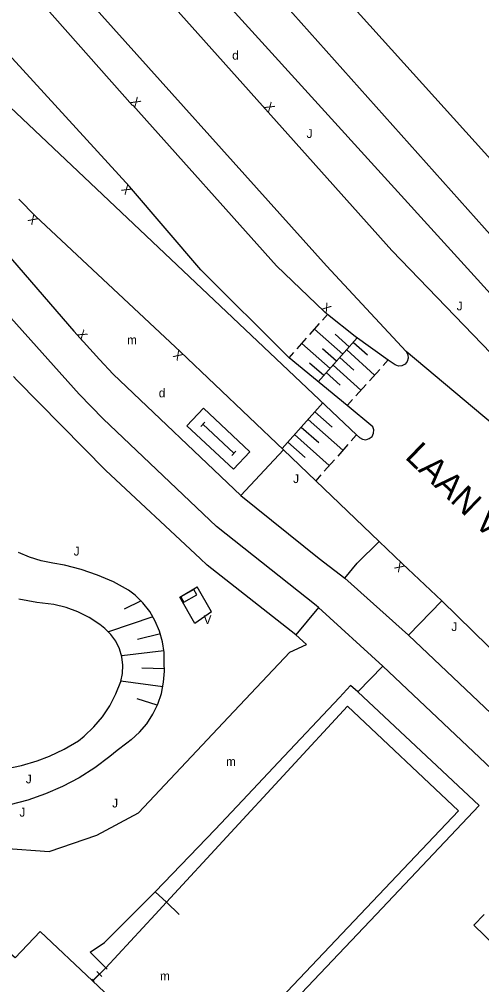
# Model space of a CAD drawing. Extents: x 134999 to 136502, y 457398 to 459002.
# Drawn here: x 135226.5 to 135252.6, y 457796 to 457850.6 of the extents above; entities that cross this region are included whole.
import ezdxf

# ---------------------------------------------------------------- set-up
doc = ezdxf.new("R2010")
doc.units = 0
for name, color, linetype in [('RI_DGTB_18', 7, 'Continuous'), ('RI_DGTB_2', 7, 'Continuous'), ('RI_DGTB_29', 7, 'Continuous'), ('RI_DGTB_30', 7, 'Continuous'), ('RI_DGTB_31', 7, 'Continuous'), ('RI_DGTB_37', 7, 'Continuous'), ('RI_DGTB_43', 7, 'Continuous'), ('RI_DGTB_48', 7, 'Continuous'), ('RI_DGTB_53', 7, 'Continuous'), ('RI_DGTB_58', 7, 'Continuous')]:
    doc.layers.add(name, color=color, linetype=linetype)

msp = doc.modelspace()

# ---------------------------------------------------------------- linework, layer by layer
at = {"layer": 'RI_DGTB_18'}
for p, q in [((135233.386, 457817.734), (135232.425, 457817.267)), ((135233.386, 457817.734), (135232.425, 457817.267)), ((135234.063, 457816.825), (135231.542, 457815.977)), ((135234.063, 457816.825), (135231.542, 457815.977)), ((135234.48, 457815.874), (135233.195, 457815.554)), ((135234.48, 457815.874), (135233.195, 457815.554)), ((135234.679, 457814.901), (135232.294, 457814.618)), ((135234.679, 457814.901), (135232.294, 457814.618)), ((135234.709, 457813.879), (135233.426, 457813.917)), ((135234.709, 457813.879), (135233.426, 457813.917)), ((135234.621, 457812.878), (135232.254, 457813.185)), ((135234.621, 457812.878), (135232.254, 457813.185)), ((135234.306, 457811.832), (135233.176, 457812.185)), ((135234.306, 457811.832), (135233.176, 457812.185))]:
    msp.add_line(p, q, dxfattribs=at)
for points in [[(135232.826, 457809.864), (135233.295, 457810.297), (135233.707, 457810.785), (135234.054, 457811.321), (135234.332, 457811.896), (135234.535, 457812.501), (135234.662, 457813.127), (135234.709, 457813.764), (135234.696, 457814.188), (135234.687, 457814.808), (135234.599, 457815.421), (135234.432, 457816.018), (135234.19, 457816.588), (135233.876, 457817.123), (135233.497, 457817.613), (135233.057, 457818.049), (135232.688, 457818.341), (135231.826, 457818.802), (135230.929, 457819.192), (135230.003, 457819.507), (135229.054, 457819.745), (135228.409, 457819.861), (135227.739, 457819.989), (135227.088, 457820.195), (135226.466, 457820.476)], [(135232.826, 457809.864), (135233.295, 457810.297), (135233.707, 457810.785), (135234.054, 457811.321), (135234.332, 457811.896), (135234.535, 457812.501), (135234.662, 457813.127), (135234.709, 457813.764), (135234.696, 457814.188), (135234.687, 457814.808), (135234.599, 457815.421), (135234.432, 457816.018), (135234.19, 457816.588), (135233.876, 457817.123), (135233.497, 457817.613), (135233.057, 457818.049), (135232.688, 457818.341), (135231.826, 457818.802), (135230.929, 457819.192), (135230.003, 457819.507), (135229.054, 457819.745), (135228.409, 457819.861), (135227.739, 457819.989), (135227.088, 457820.195), (135226.466, 457820.476)], [(135236.365, 457818.379), (135235.633, 457817.961), (135235.811, 457817.65), (135236.542, 457818.068), (135236.365, 457818.379)], [(135236.365, 457818.379), (135235.633, 457817.961), (135235.811, 457817.65), (135236.542, 457818.068), (135236.365, 457818.379)], [(135232.826, 457809.864), (135232.587, 457809.675), (135232.036, 457809.264), (135231.626, 457808.921), (135230.778, 457808.292), (135229.885, 457807.728), (135228.952, 457807.234), (135227.984, 457806.812), (135226.987, 457806.464), (135225.966, 457806.193), (135224.928, 457805.999), (135223.878, 457805.885), (135223.36, 457805.868)], [(135232.826, 457809.864), (135232.587, 457809.675), (135232.036, 457809.264), (135231.626, 457808.921), (135230.778, 457808.292), (135229.885, 457807.728), (135228.952, 457807.234), (135227.984, 457806.812), (135226.987, 457806.464), (135225.966, 457806.193), (135224.928, 457805.999), (135223.878, 457805.885), (135223.36, 457805.868)]]:
    msp.add_lwpolyline(points, dxfattribs=at)
at = {"layer": 'RI_DGTB_2'}
for points in [[(135230.648, 457796.241), (135227.689, 457799.035), (135226.273, 457797.536), (135226.034, 457797.754), (135225.913, 457797.626)], [(135234.624, 457792.299), (135234.718, 457792.398), (135230.648, 457796.241)]]:
    msp.add_lwpolyline(points, dxfattribs=at)
at = {"layer": 'RI_DGTB_29'}
for points in [[(135238.604, 457825.177), (135239.538, 457826.167), (135236.912, 457828.626), (135235.98, 457827.634), (135238.604, 457825.177)], [(135238.604, 457825.177), (135239.538, 457826.167), (135236.912, 457828.626), (135235.98, 457827.634), (135238.604, 457825.177)], [(135236.768, 457827.598), (135237.001, 457827.847)], [(135236.768, 457827.598), (135237.001, 457827.847)], [(135236.885, 457827.72), (135238.633, 457826.082)], [(135236.885, 457827.72), (135238.633, 457826.082)], [(135238.516, 457825.956), (135238.748, 457826.205)], [(135238.516, 457825.956), (135238.748, 457826.205)]]:
    msp.add_lwpolyline(points, dxfattribs=at)
at = {"layer": 'RI_DGTB_31'}
for p, q in [((135243.648, 457833.616), (135243.919, 457833.921)), ((135243.648, 457833.616), (135243.919, 457833.921)), ((135242.927, 457832.801), (135243.468, 457833.412)), ((135242.927, 457832.801), (135243.468, 457833.412)), ((135244.793, 457831.693), (135243.197, 457833.106)), ((135244.793, 457831.693), (135243.197, 457833.106)), ((135245.154, 457832.1), (135244.356, 457832.807)), ((135245.154, 457832.1), (135244.356, 457832.807)), ((135242.205, 457831.986), (135242.746, 457832.597)), ((135242.205, 457831.986), (135242.746, 457832.597)), ((135244.071, 457830.878), (135242.476, 457832.292)), ((135244.071, 457830.878), (135242.476, 457832.292)), ((135243.405, 457830.126), (135245.599, 457832.603)), ((135243.405, 457830.126), (135245.599, 457832.603)), ((135245.396, 457832.352), (135246.185, 457831.641)), ((135245.396, 457832.352), (135246.185, 457831.641)), ((135241.754, 457831.477), (135242.025, 457831.782)), ((135241.754, 457831.477), (135242.025, 457831.782)), ((135244.432, 457831.286), (135243.634, 457831.992)), ((135244.432, 457831.286), (135243.634, 457831.992)), ((135245.011, 457831.924), (135246.589, 457830.502)), ((135245.011, 457831.924), (135246.589, 457830.502)), ((135243.71, 457830.471), (135242.913, 457831.178)), ((135243.71, 457830.471), (135242.913, 457831.178)), ((135244.24, 457831.07), (135245.818, 457829.648)), ((135244.24, 457831.07), (135245.818, 457829.648)), ((135244.626, 457831.497), (135245.415, 457830.786)), ((135244.626, 457831.497), (135245.415, 457830.786)), ((135247.359, 457831.357), (135247.07, 457831.036)), ((135247.359, 457831.357), (135247.07, 457831.036)), ((135243.855, 457830.642), (135244.644, 457829.931)), ((135243.855, 457830.642), (135244.644, 457829.931)), ((135246.878, 457830.823), (135246.3, 457830.182)), ((135246.878, 457830.823), (135246.3, 457830.182)), ((135246.107, 457829.968), (135245.529, 457829.327)), ((135246.107, 457829.968), (135245.529, 457829.327)), ((135243.653, 457828.927), (135241.366, 457826.349)), ((135243.653, 457828.927), (135241.366, 457826.349)), ((135245.337, 457829.114), (135245.048, 457828.793)), ((135245.337, 457829.114), (135245.048, 457828.793)), ((135243.205, 457828.421), (135244.189, 457827.548)), ((135243.205, 457828.421), (135244.189, 457827.548)), ((135242.824, 457827.992), (135244.791, 457826.246)), ((135242.824, 457827.992), (135244.791, 457826.246)), ((135242.443, 457827.563), (135243.427, 457826.69)), ((135242.443, 457827.563), (135243.427, 457826.69)), ((135241.681, 457826.704), (135242.665, 457825.831)), ((135241.681, 457826.704), (135242.665, 457825.831)), ((135242.062, 457827.133), (135244.029, 457825.388)), ((135242.062, 457827.133), (135244.029, 457825.388)), ((135245.553, 457827.105), (135245.267, 457826.783)), ((135245.553, 457827.105), (135245.267, 457826.783)), ((135245.077, 457826.568), (135244.505, 457825.924)), ((135245.077, 457826.568), (135244.505, 457825.924)), ((135244.315, 457825.71), (135243.743, 457825.066)), ((135244.315, 457825.71), (135243.743, 457825.066)), ((135243.553, 457824.851), (135243.267, 457824.529)), ((135243.553, 457824.851), (135243.267, 457824.529))]:
    msp.add_line(p, q, dxfattribs=at)
at = {"layer": 'RI_DGTB_48'}
for p, q in [((135231.4, 457796.978), (135230.648, 457796.241)), ((135231.4, 457796.978), (135230.674, 457796.266)), ((135230.895, 457796.767), (135231.179, 457796.477)), ((135231.329, 457797.051), (135231.471, 457796.906)), ((135230.602, 457796.339), (135230.745, 457796.194))]:
    msp.add_line(p, q, dxfattribs=at)
for points in [[(135245.777, 457800), (135251.328, 457805.855), (135245.048, 457811.777), (135234.818, 457800.684)], [(135245.777, 457800), (135251.328, 457805.855), (135245.048, 457811.777), (135234.818, 457800.684)], [(135234.818, 457800.684), (135234.187, 457800)], [(135234.818, 457800.684), (135234.187, 457800)], [(135224.781, 457777.855), (135245.777, 457800)], [(135234.187, 457800), (135231.4, 457796.978)]]:
    msp.add_lwpolyline(points, dxfattribs=at)
at = {"layer": 'RI_DGTB_53'}
for p, q in [((135241.436, 457826.282), (135239.029, 457823.682)), ((135241.436, 457826.282), (135239.029, 457823.682)), ((135248.495, 457815.799), (135244.907, 457819.008)), ((135248.495, 457815.799), (135244.907, 457819.008)), ((135250.386, 457817.74), (135248.495, 457815.799)), ((135250.386, 457817.74), (135248.495, 457815.799)), ((135256.577, 457811.657), (135250.386, 457817.74)), ((135256.577, 457811.657), (135250.386, 457817.74)), ((135243.419, 457817.363), (135242.141, 457815.804)), ((135243.419, 457817.363), (135242.141, 457815.804)), ((135247.057, 457814.035), (135243.419, 457817.363)), ((135247.057, 457814.035), (135243.419, 457817.363)), ((135248.495, 457815.799), (135255.373, 457809.277)), ((135248.495, 457815.799), (135255.373, 457809.277)), ((135247.057, 457814.035), (135245.634, 457812.582)), ((135247.057, 457814.035), (135245.634, 457812.582)), ((135254.543, 457806.938), (135247.057, 457814.035)), ((135254.543, 457806.938), (135247.057, 457814.035)), ((135245.634, 457812.582), (135252.496, 457806.153)), ((135245.634, 457812.582), (135252.496, 457806.153))]:
    msp.add_line(p, q, dxfattribs=at)
for points in [[(135262.084, 457829.306), (135259.895, 457831.332), (135255.632, 457835.649), (135218.403, 457877.368), (135217.92, 457878.412), (135217.51, 457879.486), (135217.176, 457880.587), (135216.92, 457881.708), (135216.742, 457882.844), (135216.643, 457883.99), (135216.624, 457885.14), (135216.685, 457886.288), (135216.826, 457887.43), (135217.046, 457888.559), (135217.344, 457889.67), (135217.718, 457890.757), (135218.167, 457891.816), (135218.689, 457892.841), (135219.28, 457893.828), (135219.484, 457894.135), (135220.596, 457896.004)], [(135214.308, 457869.684), (135214.517, 457869.524), (135229.194, 457853.064), (135243.866, 457836.688), (135248.375, 457831.827)], [(135254.018, 457841.725), (135228.805, 457869.703)], [(135243.928, 457833.931), (135243.731, 457834.089), (135241.042, 457836.69), (135232.933, 457845.76), (135232.913, 457845.748), (135213.574, 457867.578), (135213.061, 457868.14)], [(135241.761, 457831.485), (135241.728, 457831.512), (135236.775, 457836.464), (135232.736, 457841.175), (135213.03, 457862.732)], [(135231.424, 457858.338), (135231.738, 457858.525), (135231.868, 457858.521), (135231.972, 457858.444), (135254.459, 457833.654), (135260.855, 457827.225)], [(135230.086, 457857.141), (135247.557, 457837.552), (135253.693, 457831.203), (135259.46, 457825.55)], [(135243.419, 457817.363), (135243.294, 457817.477), (135237.651, 457821.934), (135231.247, 457828.034), (135229.888, 457829.418), (135222.146, 457838.055), (135220.907, 457839.356), (135219.612, 457840.6), (135218.263, 457841.785), (135216.862, 457842.909), (135215.413, 457843.969), (135213.917, 457844.964), (135212.379, 457845.891), (135210.802, 457846.749), (135209.187, 457847.536), (135208.738, 457847.739), (135202.359, 457850.382), (135202.344, 457850.386)], [(135224.564, 457846.994), (135245.564, 457827.118)], [(135226.49, 457840.445), (135227.431, 457839.492), (135235.627, 457831.811), (135241.436, 457826.282)], [(135224.67, 457838.656), (135229.595, 457832.986), (135231.048, 457831.377), (135231.814, 457830.554), (135239.029, 457823.682)], [(135247.353, 457831.351), (135245.489, 457832.681), (135243.928, 457833.931)], [(135247.353, 457831.351), (135245.489, 457832.681), (135243.928, 457833.931)], [(135248.375, 457831.827), (135248.471, 457831.653), (135248.492, 457831.455), (135248.434, 457831.265), (135248.306, 457831.113), (135248.129, 457831.022), (135247.931, 457831.008), (135247.743, 457831.073), (135247.353, 457831.351)], [(135248.375, 457831.827), (135248.471, 457831.653), (135248.492, 457831.455), (135248.434, 457831.265), (135248.306, 457831.113), (135248.129, 457831.022), (135247.931, 457831.008), (135247.743, 457831.073), (135247.353, 457831.351)], [(135273.961, 457811.511), (135263.706, 457818.967), (135248.375, 457831.827)], [(135273.961, 457811.511), (135263.706, 457818.967), (135248.375, 457831.827)], [(135245.035, 457828.778), (135241.761, 457831.485)], [(135245.035, 457828.778), (135241.761, 457831.485)], [(135236.73, 457820.135), (135231.407, 457825.105), (135226.366, 457830.218), (135226.186, 457830.423)], [(135236.73, 457820.135), (135231.407, 457825.105), (135226.366, 457830.218), (135226.186, 457830.423)], [(135245.564, 457827.118), (135245.727, 457826.964), (135245.901, 457826.868), (135246.099, 457826.848), (135246.289, 457826.906), (135246.441, 457827.034), (135246.531, 457827.211), (135246.545, 457827.41), (135246.495, 457827.571), (135245.035, 457828.778)], [(135245.564, 457827.118), (135245.727, 457826.964), (135245.901, 457826.868), (135246.099, 457826.848), (135246.289, 457826.906), (135246.441, 457827.034), (135246.531, 457827.211), (135246.545, 457827.41), (135246.495, 457827.571), (135245.035, 457828.778)], [(135241.436, 457826.282), (135243.265, 457824.527)], [(135241.436, 457826.282), (135243.265, 457824.527)], [(135243.265, 457824.527), (135246.849, 457821.088)], [(135243.265, 457824.527), (135246.849, 457821.088)], [(135239.029, 457823.682), (135243.463, 457820.121), (135244.907, 457819.008)], [(135239.029, 457823.682), (135243.463, 457820.121), (135244.907, 457819.008)], [(135244.907, 457819.008), (135245.598, 457819.859), (135246.849, 457821.088)], [(135244.907, 457819.008), (135245.598, 457819.859), (135246.849, 457821.088)], [(135246.849, 457821.088), (135248.145, 457819.844), (135250.386, 457817.74)], [(135246.849, 457821.088), (135248.145, 457819.844), (135250.386, 457817.74)], [(135237.657, 457819.345), (135237.133, 457819.759), (135236.73, 457820.135)], [(135237.657, 457819.345), (135237.133, 457819.759), (135236.73, 457820.135)], [(135242.141, 457815.804), (135237.657, 457819.345)], [(135242.141, 457815.804), (135237.657, 457819.345)], [(135237.379, 457817.104), (135236.426, 457816.453), (135235.578, 457817.933), (135236.565, 457818.525)], [(135237.379, 457817.104), (135236.426, 457816.453), (135235.578, 457817.933), (135236.565, 457818.525)], [(135237.379, 457817.104), (135236.565, 457818.525)], [(135237.379, 457817.104), (135236.565, 457818.525)], [(135242.73, 457815.26), (135242.141, 457815.804)], [(135242.73, 457815.26), (135242.141, 457815.804)], [(135225.621, 457803.752), (135228.19, 457803.546), (135230.892, 457804.477), (135233.248, 457805.742), (135238.325, 457811.161), (135241.792, 457814.833), (135242.73, 457815.26)], [(135225.621, 457803.752), (135228.19, 457803.546), (135230.892, 457804.477), (135233.248, 457805.742), (135238.325, 457811.161), (135241.792, 457814.833), (135242.73, 457815.26)], [(135234.19, 457801.28), (135237.582, 457804.805), (135239.124, 457806.432), (135241.15, 457808.599), (135244.613, 457812.273), (135245.235, 457812.95)], [(135234.19, 457801.28), (135237.582, 457804.805), (135239.124, 457806.432), (135241.15, 457808.599), (135244.613, 457812.273), (135245.235, 457812.95)], [(135245.634, 457812.582), (135245.235, 457812.95)], [(135245.634, 457812.582), (135245.235, 457812.95)], [(135246.668, 457800), (135252.496, 457806.153)], [(135246.668, 457800), (135252.496, 457806.153)], [(135232.911, 457800), (135234.19, 457801.28)], [(135232.911, 457800), (135234.19, 457801.28)], [(135234.818, 457800.684), (135234.19, 457801.28)], [(135234.818, 457800.684), (135234.19, 457801.28)], [(135235.539, 457800), (135234.818, 457800.684)], [(135235.539, 457800), (135234.818, 457800.684)], [(135224.115, 457777.274), (135224.71, 457776.706), (135239.621, 457792.561), (135246.668, 457800)], [(135231.4, 457796.978), (135230.513, 457797.861), (135231.329, 457798.417), (135232.911, 457800)], [(135252.783, 457800), (135252.196, 457799.392), (135257.65, 457794.108), (135268.337, 457783.81), (135273.74, 457778.626)]]:
    msp.add_lwpolyline(points, dxfattribs=at)
at = {"layer": 'RI_DGTB_58'}
msp.add_lwpolyline([(135225.723, 457808.223), (135226.633, 457808.413), (135227.523, 457808.68), (135228.211, 457808.945), (135229.048, 457809.344), (135229.848, 457809.814), (135230.182, 457810.085), (135230.722, 457810.605), (135231.204, 457811.179), (135231.621, 457811.802), (135231.971, 457812.465), (135232.247, 457813.162), (135232.344, 457813.615), (135232.365, 457814.091), (135232.306, 457814.563), (135232.169, 457815.019), (135231.958, 457815.445), (135231.678, 457815.83), (135231.338, 457816.163), (135231.052, 457816.389), (135230.456, 457816.782), (135229.82, 457817.106), (135229.151, 457817.356), (135228.459, 457817.531), (135227.49, 457817.636), (135226.483, 457817.823)], dxfattribs=at)
msp.add_lwpolyline([(135225.723, 457808.223), (135226.633, 457808.413), (135227.523, 457808.68), (135228.211, 457808.945), (135229.048, 457809.344), (135229.848, 457809.814), (135230.182, 457810.085), (135230.722, 457810.605), (135231.204, 457811.179), (135231.621, 457811.802), (135231.971, 457812.465), (135232.247, 457813.162), (135232.344, 457813.615), (135232.365, 457814.091), (135232.306, 457814.563), (135232.169, 457815.019), (135231.958, 457815.445), (135231.678, 457815.83), (135231.338, 457816.163), (135231.052, 457816.389), (135230.456, 457816.782), (135229.82, 457817.106), (135229.151, 457817.356), (135228.459, 457817.531), (135227.49, 457817.636), (135226.483, 457817.823)], dxfattribs=at)

# ---------------------------------------------------------------- texts
at = {"layer": 'RI_DGTB_29'}
for p in [(135238.539, 457848.342), (135234.389, 457829.241), (135234.389, 457829.241)]:
    msp.add_text('d', height=0.5, dxfattribs=at).set_placement(p)
at = {"layer": 'RI_DGTB_30'}
for rotation, p in [(311.7977, (135232.767, 457845.946)), (310.9878, (135240.326, 457845.668)), (130.6081, (135232.899, 457840.985)), (134.6354, (135227.607, 457839.314)), (321.3089, (135243.536, 457834.245)), (321.3089, (135243.536, 457834.245)), (308.6319, (135229.733, 457832.81)), (308.6319, (135229.733, 457832.81)), (136.8599, (135235.809, 457831.64)), (136.8599, (135235.809, 457831.64)), (136.183, (135248.325, 457819.671)), (136.183, (135248.325, 457819.671))]:
    msp.add_text('X', height=0.5, rotation=rotation, dxfattribs=at).set_placement(p)
msp.add_text('V', height=0.5, dxfattribs=at).set_placement((135236.922, 457816.421))
msp.add_text('V', height=0.5, dxfattribs=at).set_placement((135236.922, 457816.421))
at = {"layer": 'RI_DGTB_31'}
for p in [(135242.743, 457843.91), (135251.225, 457834.161), (135251.225, 457834.161), (135241.984, 457824.395), (135241.984, 457824.395), (135229.579, 457820.293), (135229.579, 457820.293), (135250.927, 457816.024), (135250.927, 457816.024), (135226.877, 457807.408), (135226.877, 457807.408), (135231.756, 457806.047), (135231.756, 457806.047), (135226.516, 457805.526), (135226.516, 457805.526)]:
    msp.add_text('J', height=0.5, dxfattribs=at).set_placement(p)
at = {"layer": 'RI_DGTB_37'}
msp.add_text('LAAN VAN CHARTROISE', height=1.4, rotation=316.2344, dxfattribs=at).set_placement((135248.251, 457825.821))
msp.add_text('LAAN VAN CHARTROISE', height=1.4, rotation=316.2344, dxfattribs=at).set_placement((135248.251, 457825.821))
at = {"layer": 'RI_DGTB_43'}
for p in [(135232.599, 457832.242), (135232.599, 457832.242), (135238.192, 457808.391), (135238.192, 457808.391)]:
    msp.add_text('m', height=0.5, rotation=359.9997, dxfattribs=at).set_placement(p)
msp.add_text('m', height=0.5, dxfattribs=at).set_placement((135234.46, 457796.267))

doc.saveas('drawing.dxf')
